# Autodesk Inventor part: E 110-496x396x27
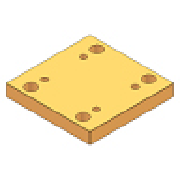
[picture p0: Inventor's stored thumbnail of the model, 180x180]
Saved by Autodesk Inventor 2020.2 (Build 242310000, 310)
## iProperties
Manager: www.cadconsulting.pl
Company: Fabian Stasiak CAD Consulting
Created: 2014-02
Part Number: E 110-496x396x27
Material: S 55 C
Description: Bottom Clamping Plate
Document SubType Name: Modeling
Designer: F.Stasiak
Standard Revision: 1
Manufacturer: DME
Language: pl-PL
Size Designation: 496x396x27
Categories: <MemberInstance><Categories><Category DisplayName="Forma wtryskowa" InternalName="349578f2-f4d4-4954-8c09-8e99297a61c0" Mnemonic="MOLD"><Category DisplayName="P
Density: 7.85 g/cm^3
Appearance: Orange (Pale)
Catalog Web Link: www.expertbooks.pl
Author: F.Stasiak
Subject: Zbiór ćwiczeń. Autodesk Inventor 2020. Kurs Professional
IsCustomPart: 1
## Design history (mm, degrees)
sketch "Sketch1"
  geometry: L1 (-198, 248)-(198, 248); L2 (198, 248)-(198, -248); L3 (198, -248)-(-198, -248); L4 (-198, -248)-(-198, 248); 5 further points
  constraints: 8 end point, 2 midpoint, 2 parallel, 1 horizontal, 1 horizontal alignment, 1 perpendicular, 1 vertical alignment
  dimensions: "d72" = 137 horizontal distance of point (0, 0) point (-137, 165) (= 0.5 x S1_W); "d73" = 165 vertical distance of point (0, 0) point (-137, 165) (= 0.5 x S1_L); "d74" = 137 horizontal distance of point (0, 0) point (-137, 208) (= 0.5 x LS_W); "d75" = 208 vertical distance of point (0, 0) point (-137, 208) (= 0.5 x LS_L); "d105" = 396 distance between parallel lines of L2 L4 (= W_); "d106" = 496 distance between parallel lines of L3 L1 (= L)
extrude "Extrusion1" new body sketch "Sketch1" distance "d20" = 27 (= H_); taper "d30" = 0 deg
hole "Hole1" sketch "Sketch1" diameter "d76" = 18 (= S1_d1); stored, may be unused: countersink angle "d80" = 90 deg, drill point angle "d82" = 0 deg; dims "d77" = 6, "d78" = 26 (= S1_d2), "d79" = 21 (= S1_k), "d81" = 27 (= H_)
pattern_linear "Rectangular Pattern1" dims "d92" = 330 (computed from S1_L, Ns), "d95" = 274 (computed from S1_W, Nw)
hole "Hole2" sketch "Sketch1" diameter "d83" = 42 (= LS_d1); stored, may be unused: countersink angle "d87" = 90 deg, drill point angle "d89" = 0 deg; dims "d84" = 6, "d85" = 26 (= S1_d2), "d86" = 21 (= S1_k), "d88" = 27 (= H_)
pattern_linear "Rectangular Pattern2" dims "d98" = 416 (computed from LS_L, Nl), "d101" = 274 (computed from LS_W, Nw)
chamfer "Chamfer1" distance "d102" = 0.5; stored, may be unused: second distance "d103" = 2, angle "d104" = 45 deg
body "Solid1"
other parameters: "L" = 496 [user parameter; used in 1 equation term], "W_" = 396 [user parameter; used in 1 equation term], "H_" = 27 [user parameter; used in 3 equation terms], "S1_W" = 274 [user parameter; used in 2 equation terms], "S1_d1" = 18 [user parameter; used in 1 equation term], "S1_d2" = 26 [user parameter; used in 2 equation terms], "S1_k" = 21 [user parameter; used in 2 equation terms], "LS_d1" = 42 [user parameter; used in 1 equation term], "LS_W" = 274 [user parameter; used in 2 equation terms], "LS_L" = 416 [user parameter; used in 2 equation terms]
